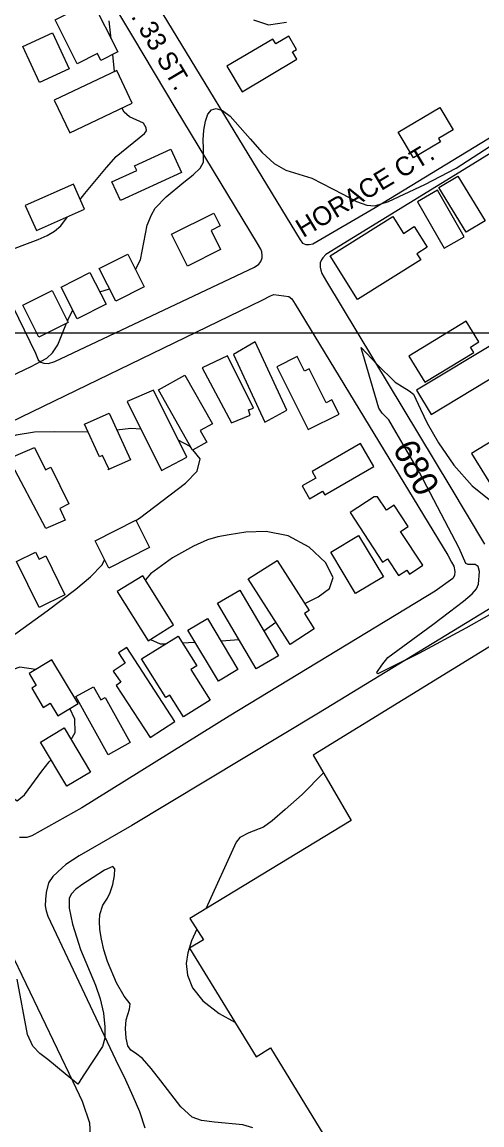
# Model space of a CAD drawing. Extents: x 79600 to 91800, y 75600 to 84400.
# Drawn here: x 82008 to 82374, y 81370 to 82248 of the extents above; entities that cross this region are included whole.
import ezdxf

# ---------------------------------------------------------------- set-up
doc = ezdxf.new("R2010")
doc.units = 0
for name, color, linetype in [('084-085$0$BLDG', 7, 'Continuous'), ('084-085$0$GRID', 7, 'Continuous'), ('084-085$0$INDEX', 7, 'Continuous'), ('084-085$0$INDXLBL', 7, 'Continuous'), ('084-085$0$INTER', 7, 'Continuous'), ('084-085$0$ROAD', 7, 'Continuous'), ('084-085$0$ROAD-NAME', 7, 'Continuous')]:
    doc.layers.add(name, color=color, linetype=linetype)

msp = doc.modelspace()

# ---------------------------------------------------------------- linework, layer by layer
at = {"layer": '084-085$0$BLDG'}
for points in [[(82070.39, 82217.1), (82067.62, 82222.6), (82051.6, 82214.53), (82034.04, 82249.36), (82063.44, 82264.19), (82083.78, 82223.85)], [(82021.48, 82199.57), (82008.3, 82228.3), (82032.01, 82239.18), (82045.19, 82210.45)], [(82222.89, 82223.86), (82226.15, 82225.8), (82219.87, 82236.37), (82209.51, 82230.22), (82207.15, 82234.18), (82170.72, 82212.53), (82182.79, 82192.23), (82226.32, 82218.11)], [(82083.05, 82209.2), (82033.32, 82185.57), (82045.66, 82159.6), (82095.39, 82183.23)], [(82339.06, 82154.96), (82340.56, 82152.44), (82319.02, 82139.56), (82306.87, 82159.89), (82340.04, 82179.72), (82350.68, 82161.92)], [(82079.24, 82120.51), (82098.94, 82129.57), (82097.21, 82133.33), (82126.05, 82146.59), (82134.68, 82127.84), (82086.13, 82105.52)], [(82360.94, 82080.34), (82339.37, 82115.94), (82354.49, 82125.1), (82376.06, 82089.5)], [(82019.07, 82081.66), (82057.37, 82098.69), (82048.52, 82118.6), (82010.22, 82101.57)], [(82359.39, 82076.69), (82338.09, 82113.73), (82322.22, 82104.59), (82343.51, 82067.56)], [(82160.23, 82095.63), (82165.33, 82085.4), (82158.08, 82081.78), (82165.69, 82066.5), (82139.21, 82053.29), (82126.49, 82078.8)], [(82311.12, 82079.36), (82319.75, 82084.79), (82330.04, 82068.43), (82321.85, 82063.28), (82324.88, 82058.47), (82274.63, 82026.85), (82252.78, 82061.57), (82302.6, 82092.91)], [(82091.79, 82062.98), (82104.91, 82036.85), (82082.23, 82025.47), (82069.11, 82051.6)], [(82061.71, 82048.35), (82074.56, 82023.06), (82051.62, 82011.41), (82038.77, 82036.7)], [(82031.64, 82033.95), (82044.31, 82008.53), (82021.01, 81996.91), (82008.33, 82022.33)], [(82364.42, 81988.88), (82371.15, 81992.98), (82361.03, 82009.6), (82315.37, 81981.82), (82328.08, 81960.94), (82367.01, 81984.63)], [(82218.47, 81938.71), (82193.25, 81992.97), (82175.9, 81982.91), (82200.81, 81929.27)], [(82333.31, 81935.22), (82400.23, 81975.73), (82388.52, 81995.07), (82321.6, 81954.56)], [(82191.72, 81940.4), (82171.09, 81981.94), (82151.09, 81972.33), (82174.22, 81928.63), (82189.27, 81934.64), (82187.84, 81938.98)], [(82259.87, 81935.59), (82254.18, 81946.93), (82249.64, 81944.65), (82236.06, 81971.73), (82232.29, 81969.84), (82226.54, 81981.32), (82210.32, 81973.18), (82235.34, 81923.29)], [(82149.52, 81922.43), (82154.67, 81913.27), (82143.33, 81906.9), (82116.36, 81954.91), (82137.28, 81966.66), (82159.1, 81927.81)], [(82138.79, 81901.2), (82112.33, 81954.67), (82091.4, 81945.52), (82118.65, 81890.66)], [(82076.02, 81891.14), (82076.74, 81891.87), (82071.81, 81902.67), (82069.2, 81901.48), (82057.35, 81927.46), (82076.93, 81936.39), (82093.86, 81899.28)], [(82365.3, 81904.26), (82385.03, 81872.01), (82387.44, 81873.48), (82396.15, 81859.25), (82416.71, 81871.83), (82388.27, 81918.31)], [(82026.74, 81844.52), (81997.16, 81900.15), (82017.63, 81908.99), (82026.45, 81891.32), (82030.47, 81893.36), (82044.81, 81864.23), (82037.84, 81860.29), (82042.09, 81851.15)], [(82238.46, 81889.91), (82241.49, 81884.68), (82230.57, 81878.35), (82236.51, 81868.11), (82246.82, 81874.09), (82248.51, 81871.18), (82287.59, 81893.85), (82276.94, 81912.22)], [(82290.57, 81869.67), (82287.76, 81869.65), (82268.72, 81857.12), (82294.59, 81817.79), (82298.39, 81820.29), (82307.12, 81807.02), (82313.83, 81811.43), (82315.96, 81808.2), (82326.63, 81815.21), (82308.87, 81842.21), (82314.95, 81846.21), (82303.85, 81863.08), (82297.6, 81858.97)], [(82098.13, 81851.07), (82109.15, 81829.37), (82076.79, 81812.93), (82065.77, 81834.63)], [(82275.42, 81838.94), (82295.16, 81806.13), (82273.07, 81792.83), (82253.33, 81825.64)], [(82018.44, 81825.72), (82021.25, 81820.01), (82026.58, 81822.64), (82041.81, 81791.74), (82021.32, 81781.64), (82003.28, 81818.25)], [(82210.67, 81819.04), (82236.17, 81779.14), (82232.41, 81776.74), (82240.22, 81764.53), (82221.04, 81752.26), (82187.72, 81804.37)], [(82128.32, 81767.71), (82103.68, 81806.93), (82083.46, 81794.22), (82108.1, 81755.01)], [(82181, 81795.53), (82211.6, 81743.21), (82193.86, 81732.84), (82163.26, 81785.15)], [(82155.12, 81772.9), (82179.45, 81732.23), (82163.89, 81722.93), (82139.57, 81763.6)], [(82642.18, 81416.5), (82421.62, 81776.27), (82239.33, 81664.11), (82269.66, 81612.06), (82141.27, 81534.14), (82152.1, 81516.95), (82140.79, 81510.5), (82193.89, 81423.92), (82205.35, 81430.99), (82320.2, 81242.81), (82435.11, 81313.19), (82441.71, 81301.89), (82489.73, 81331.73), (82481.56, 81343.81), (82532.85, 81372.58), (82490.73, 81443.37), (82503.9, 81450.6), (82550.71, 81374.56), (82584.79, 81395.3), (82591.84, 81386.01), (82602.68, 81392.15), (82610.4, 81377.11), (82625.57, 81387.32), (82617.86, 81401.57)], [(82141.97, 81732.23), (82157.23, 81707.73), (82136.09, 81694.56), (82125.27, 81711.93), (82121.99, 81709.89), (82102.79, 81740.71), (82131.87, 81758.82), (82146.63, 81735.13)], [(82084.48, 81745.48), (82089.84, 81737.26), (82080.32, 81731.05), (82086.2, 81722.04), (82082.48, 81719.62), (82109.58, 81678.04), (82129.34, 81690.92), (82091.01, 81749.73)], [(82013.26, 81728.96), (82018.97, 81719.48), (82015.41, 81717.34), (82024.6, 81702.06), (82030.06, 81705.34), (82036.07, 81695.36), (82052.22, 81705.07), (82031.31, 81739.82)], [(82064.52, 81718.46), (82070.28, 81708.09), (82073.86, 81710.08), (82093.83, 81674.19), (82076.24, 81664.4), (82050.51, 81710.66)], [(82043.39, 81639.33), (82022.34, 81674.48), (82041.23, 81685.79), (82062.28, 81650.64)]]:
    msp.add_lwpolyline(points, close=True, dxfattribs=at)
at = {"layer": '084-085$0$GRID'}
msp.add_line((85000, 82000), (80000, 82000), dxfattribs=at)
at = {"layer": '084-085$0$INDEX'}
msp.add_lwpolyline([(82398.37, 81786.39), (82360.64, 81765.09), (82323.3, 81745.11), (82299.34, 81733.01), (82290.62, 81728.9), (82289.96, 81729.83), (82293.88, 81735.71), (82298.82, 81741.72), (82334.61, 81768.01), (82347.73, 81778.03), (82358.8, 81786.7), (82365.68, 81792.45), (82369.16, 81796.36), (82370.74, 81800.2), (82371.69, 81810.37), (82370.61, 81814.25), (82368.22, 81815.8), (82362.55, 81815.78), (82360.87, 81816.59), (82355.55, 81828.95), (82323.89, 81889.04), (82305.39, 81920.84), (82299.55, 81930.95), (82294.25, 81936.4), (82291.58, 81940.17), (82278.86, 81983.93), (82277.82, 81987.15), (82277.58, 81988.53), (82289.9, 81975.19), (82304.55, 81960.89), (82315.67, 81954.17), (82319.21, 81951.41), (82324.66, 81939.56), (82329.93, 81928.25), (82338.89, 81912.6), (82351.13, 81894.99), (82365.8, 81878.44), (82381.96, 81865.57)], dxfattribs=at)
at = {"layer": '084-085$0$INTER'}
for p, q in [((82081.22, 82208.33), (82079.8, 82221.85)), ((82069.6, 82032.82), (82077.24, 82035.4)), ((82135.19, 81753.49), (82145.29, 81754.03)), ((82049.69, 81692.65), (82045.74, 81701.17))]:
    msp.add_line(p, q, dxfattribs=at)
for points in [[(82078.5, 82234.31), (82077, 82248.7)], [(82191.78, 82249.33), (82203.75, 82245.46), (82217.98, 82247.68)], [(82097.98, 82050.65), (82101.9, 82058.49), (82107.27, 82085.96), (82110.62, 82094.09), (82113.67, 82099.51), (82122.26, 82108.57), (82136.47, 82120.08), (82143.9, 82125.96), (82149.45, 82131.38), (82151.99, 82136.14), (82151.94, 82146.64), (82151.85, 82153.83), (82152.37, 82161.65), (82153.56, 82168.86), (82155.5, 82174.41), (82158.31, 82177.84), (82162.12, 82178.87), (82167.06, 82177.2), (82173.21, 82172.66), (82189.28, 82154.74), (82198.69, 82143.82), (82208.28, 82134.94), (82217.68, 82129.85), (82238.22, 82123.3), (82262.84, 82110.61), (82273.78, 82104.9), (82282.07, 82101.93), (82288.37, 82101.43), (82299.14, 82104.74), (82328.2, 82118.26), (82353.2, 82131.43), (82448.65, 82193.19)], [(82053.97, 82106.34), (82057.62, 82111.27), (82074.9, 82131.97), (82082.45, 82140.6), (82105.01, 82159.02), (82106.79, 82161.06), (82106.46, 82163.48), (82104.27, 82167.05), (82093.26, 82172.17), (82088.93, 82175.99), (82087.17, 82179.33)], [(81981.63, 82023.92), (81985.24, 82024.88), (81992.39, 82029.59), (81995.26, 82033.84), (81996.23, 82039.44), (81992.9, 82056.11), (81991.73, 82059.57), (81991.15, 82062.01), (81991.53, 82063.65), (82020.58, 82074.48), (82027.59, 82077.71), (82033.46, 82081.28), (82038.44, 82085.39), (82043.85, 82092.68)], [(82043.8, 82009.55), (82044.29, 82010.76), (82047.97, 82018.61)], [(82060.21, 81921.18), (82033.46, 81921.58), (82017.63, 81921.19), (82002.91, 81918.71), (81971.79, 81908.29), (81953.19, 81901.63), (81935.49, 81896.47), (81922.77, 81895.37), (81917.83, 81899.89), (81918.43, 81907.58), (81922.91, 81919.67), (81928.53, 81928.33), (81943.27, 81946.28), (81952.07, 81954.41), (81960.21, 81958.95), (81980.54, 81961.3), (81986.53, 81962), (81998.75, 81965.65), (82014.89, 81973.38), (82023.01, 81977.6), (82027.34, 81980.21), (82031.83, 81984.25), (82036.21, 81990.76), (82043.16, 82007.95)], [(82102.35, 81923.48), (82094.15, 81924.03), (82083.08, 81922.9)], [(82142.44, 81908.47), (82141.4, 81909.76), (82131.99, 81914.94)], [(82098.28, 81850.76), (82101.09, 81852.61), (82137.78, 81880.71), (82147.01, 81890.17), (82149.28, 81900.05), (82143.6, 81907.05)], [(82232.61, 81784.72), (82243.28, 81790.04), (82252.3, 81796.62), (82255.22, 81805.6), (82249.17, 81817.52), (82236.16, 81829.71), (82219.4, 81838.74), (82201.88, 81842.15), (82185.66, 81841.54), (82172.56, 81839.5), (82163.45, 81837.87), (82155.27, 81835.45), (82143.98, 81830.32), (82127.3, 81821.06), (82109.84, 81808.48), (82105.81, 81803.53)], [(81963.08, 81740.4), (81964.36, 81739.43), (81968.83, 81738.33), (82003.94, 81761.66), (82027.6, 81778.98), (82050.4, 81796.1), (82062.24, 81805.94), (82071.46, 81815.59), (82073.4, 81819.6)], [(82199.99, 81763.05), (82200.13, 81763.12), (82209.73, 81769.95)], [(82110, 81756.2), (82110.01, 81756.19), (82117.58, 81752.56), (82122.22, 81752.81)], [(82165.76, 81755.11), (82166.33, 81755.14), (82180.2, 81756.19)], [(82018.44, 81732.08), (82018.38, 81732.12), (82005.83, 81734.05), (81994.62, 81730), (81977.54, 81717.58), (81972.36, 81712), (81969.9, 81706.02), (81970.37, 81698.97), (81973.3, 81690.75), (81983.88, 81671.01), (81989.77, 81659.96), (81997.75, 81637.97), (82000.32, 81630.1), (82003.91, 81627.7), (82009.62, 81632.36), (82023.45, 81651.23), (82029.2, 81658.84), (82030.79, 81660.37)], [(82046.77, 81676.54), (82050, 81682.01), (82049.69, 81692.65)], [(82247.57, 81649.98), (82230.42, 81632.86), (82217.11, 81620.67), (82206.65, 81611.77), (82199.77, 81606.67), (82188.23, 81602.19), (82180.91, 81598.43), (82177.96, 81594.91), (82153.91, 81541.81)], [(82191.37, 81367.26), (82183.38, 81369.8), (82160.88, 81371.82), (82150.34, 81373.25), (82143.04, 81375.98), (82133.96, 81384.19), (82117.98, 81404.82), (82110.5, 81414.67), (82103.42, 81422.67), (82097.98, 81426.9), (82094.21, 81429.25), (82091.81, 81432.57), (82090.51, 81438.84), (82090.1, 81446.58), (82090.4, 81453.45), (82093.13, 81461.86), (82093.79, 81466.19), (82088.88, 81472.26), (82082.91, 81482.85), (82075.8, 81499.91), (82072.84, 81509.11), (82070.8, 81517.68), (82069.66, 81525.33), (82069.32, 81531.88), (82069.64, 81537.23), (82071.89, 81544.71), (82075.63, 81550.19), (82077.77, 81554.61), (82079.85, 81561.15), (82081.29, 81568.16), (82081.44, 81573.43), (82079.84, 81575.33), (82073.33, 81572.45), (82055.38, 81560.88), (82050.2, 81557), (82046.94, 81553.61), (82045.2, 81550.22), (82045.17, 81542.22), (82047.9, 81529.54), (82054.31, 81509.27), (82066.02, 81480.86), (82069.75, 81469.95), (82072.38, 81458.61), (82073.66, 81447.81), (82073.45, 81438.71), (82071.66, 81432.06), (82057.36, 81410.39), (82054.52, 81405.76), (82052.89, 81403.14), (82052.18, 81402.09), (82042.06, 81410.26), (82028.09, 81421.72), (82021.75, 81426.55), (82016.38, 81432.39), (82011.95, 81441.72), (82003.71, 81485.71)], [(82146.65, 81525.6), (82142.63, 81516.15), (82139.51, 81506.72), (82138.38, 81498.16), (82139.32, 81488.84), (82143.3, 81478.78), (82151.51, 81468.46), (82164.53, 81458.43), (82176.91, 81451.62)]]:
    msp.add_lwpolyline(points, dxfattribs=at)
at = {"layer": '084-085$0$ROAD'}
for points in [[(82096.68, 82292.11), (82228.96, 82074.35), (82230.85, 82071.56), (82233.49, 82070.65), (82236.14, 82070.51), (82238.93, 82070.99), (82288.66, 82100.07), (82490.93, 82223.4)], [(82050.54, 82285.14), (81929.95, 82226.85), (81912.43, 82218.81), (81909.96, 82216), (81909.2, 82213.66), (81908.91, 82210.86), (81909.23, 82208.68), (82018.4, 81984.09), (82020.61, 81978.81), (82022.64, 81976.81), (82025.13, 81976.2), (82028.71, 81975.91), (82033.83, 81977.34), (82192.56, 82052.66), (82196.12, 82055.02), (82197.67, 82057.05), (82198.74, 82059.86), (82198.72, 82061.88), (82198.39, 82064.83), (82197.6, 82066.84), (82195.09, 82071.49), (82130.2, 82178.21), (82095.79, 82236.14), (82068.6, 82281.99)], [(82482.8, 82206.55), (82359.52, 82130.37), (82249.25, 82062.51), (82246.93, 82060), (82245.85, 82058.44), (82244.94, 82056.1), (82244.96, 82052.53), (82245.29, 82050.2), (82246.24, 82047.41), (82250.01, 82041.21), (82348.05, 81878.27), (82375.55, 81831.96)], [(81963.19, 81912.06), (82198.64, 82026.27), (82205.46, 82029.74), (82207.94, 82030.84), (82220.07, 82029.21), (82222.42, 82027.35), (82225.09, 82023.17), (82346.53, 81823.38), (82349.37, 81817.8), (82351.1, 81814.54), (82352.06, 81810.35), (82351.61, 81807.08), (82350.38, 81804.59), (82336.3, 81794.7), (82172.43, 81695.1), (82055.35, 81622.22), (82015.38, 81599.73), (82011.5, 81598.62), (82008.86, 81598.44), (82005.75, 81598.42)], [(82403.93, 81795.29), (82243.47, 81697.41), (82094.93, 81608.16), (82053.26, 81583.8), (82042.58, 81576.89), (82039.49, 81574.23), (82032.22, 81567.5), (82028.68, 81562.34), (82026.86, 81554.71), (82026.43, 81549.11), (82026.15, 81544.14), (82026.8, 81540.25), (82028.22, 81535.91), (82082.12, 81421.82), (82089.99, 81405.54), (82095.83, 81392.68), (82101.04, 81380.43), (82105.47, 81367.39)], [(81700.91, 81261.11), (82047.22, 81260.84), (82051.88, 81261.33), (82056.38, 81263.38), (82059, 81265.89), (82060.37, 81271.02), (82061.39, 81281.91), (82061.94, 81366.5), (82061.6, 81371), (82059.86, 81376.59), (82057.96, 81382.02), (82055.74, 81388.38), (82048.34, 81403.88), (81973.34, 81560.13), (81943.08, 81624.93), (81939.79, 81628.95), (81938.39, 81629.41), (81932.64, 81629.37), (81928.6, 81627.79), (81694.15, 81514.46)]]:
    msp.add_lwpolyline(points, dxfattribs=at)

# ---------------------------------------------------------------- texts
at = {"layer": '084-085$0$INDXLBL'}
msp.add_text('680', height=20, rotation=297.65536, dxfattribs=at).set_placement((82302.12, 81908.25))
at = {"layer": '084-085$0$ROAD-NAME'}
for s, rotation, p in [('W. 33 ST.', 300.88308, (82084.37, 82268.41)), ('HORACE CT.', 31.09021, (82231.33, 82075.59))]:
    msp.add_text(s, height=15, rotation=rotation, dxfattribs=at).set_placement(p)

doc.saveas('drawing.dxf')
